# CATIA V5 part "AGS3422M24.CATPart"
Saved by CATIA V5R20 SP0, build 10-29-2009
Part number: AGS3422M24
Definition: NONE
Nomenclature: AGS3422M24
Source: Unknown
Description: AGS3422M24
Bounding box of the stored display mesh (mm): x -39 to 45, y -37 to 37, z -37 to 37
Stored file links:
  C:\Users\Utente\Desktop\IO LAVORO\3D X SITO CF\X SITO\PLASTICA\AGS\AGS3422M24.CATPart
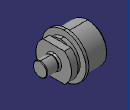
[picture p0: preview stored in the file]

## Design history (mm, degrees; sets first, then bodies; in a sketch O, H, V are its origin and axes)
Body1 "AGS3422M24" (main body)
  Solid1: solid without history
